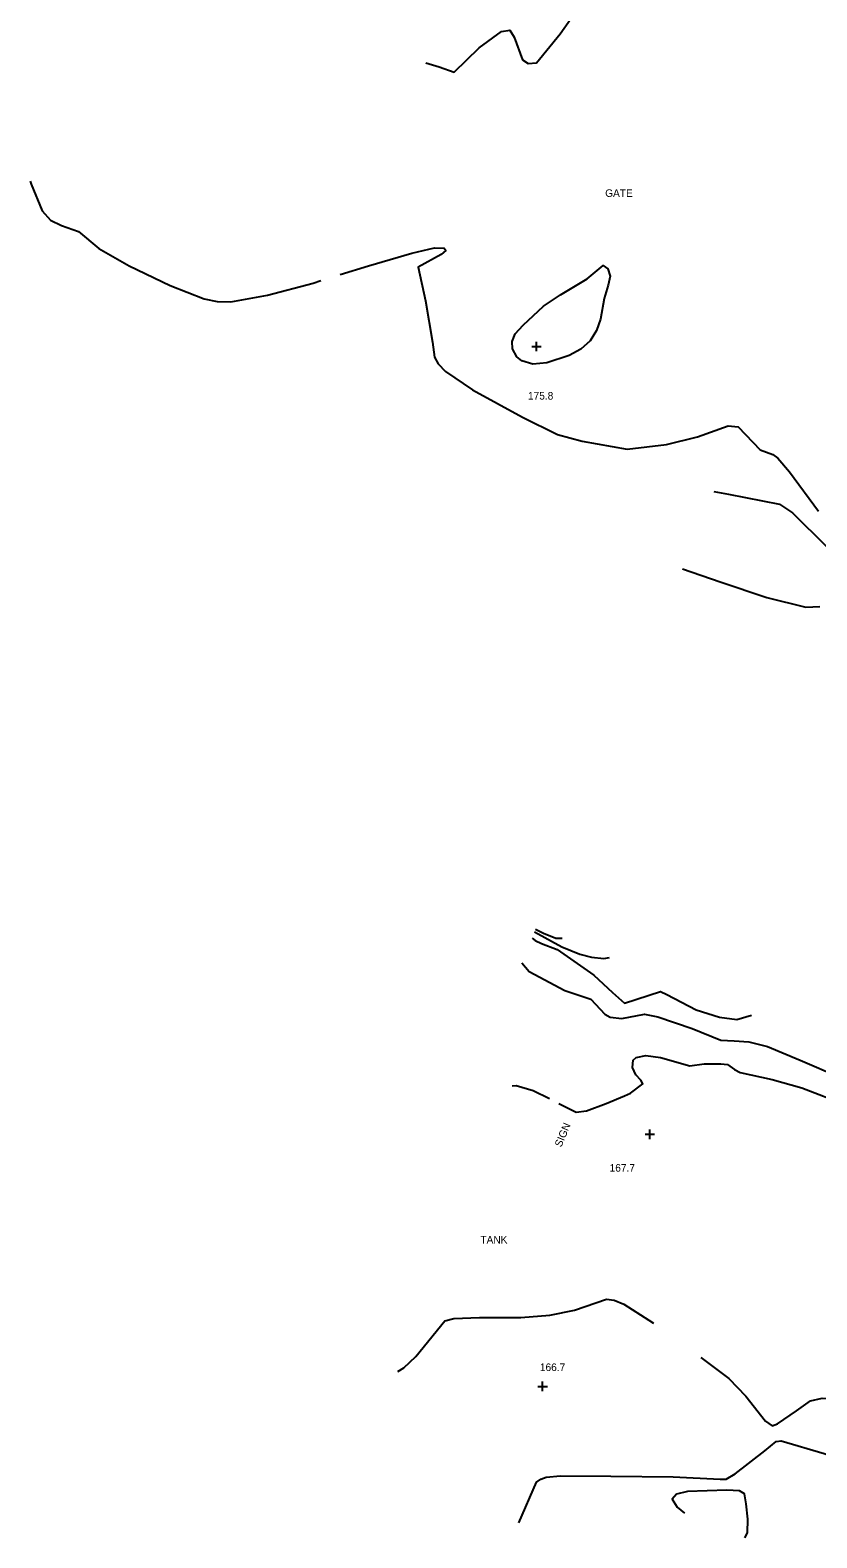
# Model space of a CAD drawing. Extents: x 1475150 to 2003689, y 770235 to 1112803.
# Drawn here: x 1996766.4 to 1996974, y 775760.7 to 776158.5 of the extents above; entities that cross this region are included whole.
import ezdxf

# ---------------------------------------------------------------- set-up
doc = ezdxf.new("R2010")
doc.units = 0
for name, color, linetype in [('RD_DTM_Major1', 7, 'Continuous'), ('RD_DTM_Minor1', 7, 'Continuous'), ('RD_DTM_Spot_Elev', 7, 'Continuous'), ('RD_TX_Misc1', 7, 'Continuous')]:
    doc.layers.add(name, color=color, linetype=linetype)

msp = doc.modelspace()

# ---------------------------------------------------------------- linework, layer by layer
at = {"layer": 'RD_DTM_Major1'}
for points in [[(1996946.85, 776036.74), (1996950.65, 776036.02), (1996964.16, 776033.44), (1996967.59, 776031.16), (1996976.58, 776022.29)], [(1996898.83, 775918.89), (1996899.69, 775918.34), (1996901.31, 775917.52), (1996905.48, 775915.92), (1996915.17, 775909.14), (1996920.05, 775904.62), (1996923.28, 775901.74), (1996932.72, 775904.82), (1996934.43, 775904.03), (1996942.13, 775900.01), (1996948.3, 775898.09), (1996952.88, 775897.43), (1996956.77, 775898.61)]]:
    msp.add_lwpolyline(points, dxfattribs=at)
at = {"layer": 'RD_DTM_Minor1'}
for points in [[(1996870.78, 776149.82), (1996874.32, 776148.84), (1996878.29, 776147.36), (1996884.92, 776153.83), (1996890.79, 776158.13), (1996893, 776158.45), (1996894.15, 776156.63), (1996896.3, 776150.64), (1996897.86, 776149.64), (1996900.01, 776149.87), (1996906.23, 776157.5), (1996908.95, 776161.4)], [(1996766.39, 776118.66), (1996766.63, 776117.86), (1996769.54, 776110.79), (1996771.73, 776108.32), (1996774.63, 776106.9), (1996779.15, 776105.36), (1996784.5, 776100.87), (1996792.52, 776096.28), (1996803.34, 776091.13), (1996812.28, 776087.61), (1996815.76, 776086.87), (1996819.34, 776086.8), (1996829.07, 776088.55), (1996841.05, 776091.75), (1996843.11, 776092.4)], [(1996848.19, 776093.98), (1996855.64, 776096.31), (1996867.13, 776099.66), (1996873.12, 776101.07), (1996875.65, 776100.98), (1996876.12, 776100.37), (1996874.88, 776099.29), (1996868.77, 776095.91), (1996870.73, 776087.04), (1996872.6, 776076.19), (1996873.11, 776072.24), (1996874.06, 776070.41), (1996876.01, 776068.4), (1996883.12, 776063.62), (1996896.3, 776056.36), (1996905.52, 776051.82), (1996912.07, 776050.06), (1996923.9, 776047.93), (1996934.32, 776049.16), (1996942.51, 776051.17), (1996950.59, 776054.09), (1996953.25, 776053.79), (1996959.04, 776047.73), (1996962.37, 776046.5), (1996963.74, 776045.59), (1996966.81, 776041.98), (1996974.43, 776031.57)], [(1996919.45, 776093.53), (1996918.9, 776091.23), (1996917.9, 776087.7), (1996916.87, 776082.19), (1996915.87, 776079.21), (1996914.19, 776076.5), (1996911.68, 776074.28), (1996908.65, 776072.6), (1996902.72, 776070.67), (1996899.04, 776070.33), (1996896.11, 776071.22), (1996894.83, 776072.28), (1996893.69, 776074.4), (1996893.59, 776076.36), (1996894.4, 776078.34), (1996896.5, 776080.67), (1996901.85, 776085.66), (1996906.34, 776088.68), (1996913.36, 776092.89), (1996917.6, 776096.42), (1996918.87, 776095.53), (1996919.45, 776093.53)], [(1996938.54, 776016.34), (1996948.46, 776012.92), (1996960.84, 776008.81), (1996971.11, 776006.21), (1996974.82, 776006.4)], [(1996899.79, 775921.25), (1996901.87, 775920.27), (1996905.11, 775918.93), (1996906.78, 775918.92)], [(1996899.52, 775920.58), (1996906.72, 775916.6), (1996911.48, 775914.66), (1996914.54, 775913.87), (1996917.76, 775913.59), (1996919.24, 775913.85)], [(1996896.18, 775912.37), (1996898.1, 775910.09), (1996907.51, 775905.07), (1996914.31, 775902.84), (1996918.05, 775898.87), (1996919.49, 775898.04), (1996922.53, 775897.72), (1996928.49, 775898.9), (1996932.01, 775898.2), (1996941.1, 775895.08), (1996948.65, 775892.02), (1996952.19, 775891.79), (1996956.02, 775891.59), (1996960.97, 775890.36), (1996969.63, 775886.75), (1996980.28, 775882.15)], [(1996905.93, 775875.32), (1996910.49, 775873.05), (1996913.2, 775873.35), (1996918.38, 775875.33), (1996923.28, 775877.32), (1996924.83, 775878.06), (1996928.1, 775880.5), (1996927.51, 775881.42), (1996926.22, 775882.83), (1996925.38, 775884.77), (1996925.51, 775886.76), (1996926.3, 775887.41), (1996928.86, 775887.94), (1996932.72, 775887.42), (1996940.44, 775885.26), (1996944.28, 775885.73), (1996948.65, 775885.76), (1996950.4, 775885.58), (1996952.3, 775884.28), (1996953.75, 775883.45), (1996962.18, 775881.65), (1996970.02, 775879.39), (1996981.95, 775874.82)], [(1996893.56, 775879.99), (1996894.61, 775880.01), (1996899.11, 775878.72), (1996903.41, 775876.58)], [(1996863.39, 775804.58), (1996864.99, 775805.57), (1996868.16, 775808.53), (1996875.83, 775817.92), (1996878.24, 775818.59), (1996884.96, 775818.83), (1996895.92, 775818.88), (1996903.57, 775819.48), (1996910.07, 775820.77), (1996918.48, 775823.7), (1996920.55, 775823.45), (1996923.07, 775822.37), (1996929.65, 775818.16), (1996930.86, 775817.31)], [(1996943.42, 775808.28), (1996950.77, 775802.79), (1996955.26, 775798.05), (1996960.41, 775791.47), (1996962.21, 775790.27), (1996963.64, 775790.81), (1996968.6, 775794.21), (1996972.32, 775796.84), (1996975.37, 775797.55), (1996979.23, 775797.25), (1996985.79, 775795.61), (1996989.09, 775794.26), (1996990.24, 775793.08), (1996989.91, 775791.67), (1996991.08, 775789.29), (1996998.24, 775781.81), (1997000.14, 775780.76), (1997001.08, 775781.46), (1997004.25, 775785.89), (1997007.15, 775792.22), (1997007.74, 775793.51)], [(1996895.35, 775764.67), (1996900.01, 775775.38), (1996901.14, 775776.16), (1996902.56, 775776.75), (1996906.36, 775777.09), (1996919.6, 775776.99), (1996936.07, 775776.81), (1996948.52, 775776.21), (1996950.08, 775776.15), (1996952.42, 775777.56), (1996960.29, 775783.69), (1996963.24, 775786.14), (1996964.57, 775786.31), (1996975.93, 775783), (1996989.02, 775778.64), (1996993.94, 775777.28), (1996998.11, 775777.09), (1997001.26, 775778.28), (1997004.2, 775780.87), (1997008.47, 775786.91), (1997011.42, 775792.03)], [(1996955.02, 775760.71), (1996955.74, 775762.03), (1996955.76, 775765.63), (1996955.33, 775769.72), (1996954.93, 775772.34), (1996953.61, 775773.1), (1996950.22, 775773.29), (1996939.86, 775772.96), (1996936.95, 775772.25), (1996935.85, 775770.89), (1996937.17, 775768.76), (1996939.09, 775767.19)]]:
    msp.add_lwpolyline(points, dxfattribs=at)
at = {"layer": 'RD_DTM_Spot_Elev'}
for p, q in [((1996900, 776073.75), (1996900, 776076.25)), ((1996898.75, 776075), (1996901.25, 776075)), ((1996928.66, 775867.18), (1996931.16, 775867.18)), ((1996929.91, 775865.93), (1996929.91, 775868.43)), ((1996901.63, 775799.42), (1996901.63, 775801.92)), ((1996900.38, 775800.67), (1996902.88, 775800.67))]:
    msp.add_line(p, q, dxfattribs=at)

# ---------------------------------------------------------------- texts
for s, p in [('175.8', (1996897.76, 776061.01)), ('167.7', (1996919.31, 775857.32)), ('166.7', (1996900.91, 775804.72))]:
    msp.add_text(s, height=2, dxfattribs=at).set_placement(p)
at = {"layer": 'RD_TX_Misc1'}
for s, p in [('GATE', (1996918.14, 776114.48)), ('TANK', (1996885.21, 775838.36))]:
    msp.add_text(s, height=2, dxfattribs=at).set_placement(p)
msp.add_text('SIGN', height=2, rotation=67.249, dxfattribs=at).set_placement((1996906.55, 775863.64))

doc.saveas('drawing.dxf')
